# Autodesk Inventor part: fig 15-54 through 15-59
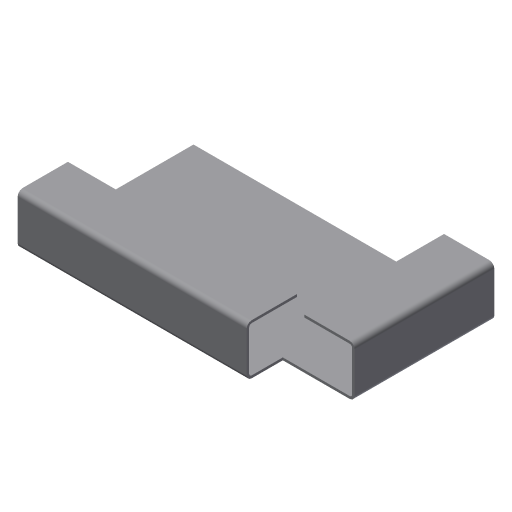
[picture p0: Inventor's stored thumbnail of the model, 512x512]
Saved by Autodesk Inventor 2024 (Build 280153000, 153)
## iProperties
Created: 2008-06
Part Number: fig 15-54 through 15-59
Material: Generic
Document SubType Name: Sheet Metal
Designer: CADCIM
Density: 1 g/cm^3
Sheet Metal Rule: Default_mm
Appearance: Default
Author: CADCIM
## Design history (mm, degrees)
node "Face1"
  sketch "Sketch1"
    geometry: L1 (-32.219, 35.011)-(27.554, 35.011); L2 (27.554, 35.011)-(27.554, 7.255); L3 (13.281, 0.063)-(-32.219, 0.063); L4 (-32.219, 0.063)-(-32.219, 35.011); L5 (13.281, 0.063)-(13.281, 7.255); L6 (13.281, 7.255)-(27.554, 7.255)
    constraints: 12 end point, 2 parallel, 2 perpendicular, 1 horizontal, 1 vertical
node "Flange5"
node "Flange6"
node "Flange7"
node "Flange8"
body "Solid1"
face "Plate1" dims "d90" = 0.5 (= Thickness)
sketch "Sketch6"
  geometry: L1 (0, 10)-(-45.501, 10); L2 (-45.501, 10)-(-45.501, 0); 1 other entity
  constraints: 4 end point, 4 other
face "Plate6" dims "d50" = 0.5 (= BendReliefWidth), "d51" = 0.25 (= BendReliefDepth), "d52" = 1 (= MinimumRemnant), "d53" = 0.5 (= BendRadius), "d54" = 10, "d55" = 90 deg, "d56" = 0.5 (= BendRadius), "d57" = 2 (= CornerReliefSize), "d58" = 0.5 (= GapSize), "d59" = 0.5 (= JacobiRadiusSize), "d90" = 0.5 (= Thickness), "SeamGap" = 0.01
bend "Bend5" dims "d50" = 0.5 (= BendReliefWidth), "d51" = 0.25 (= BendReliefDepth), "d52" = 1 (= MinimumRemnant), "d53" = 0.5 (= BendRadius), "d54" = 10, "d55" = 90 deg, "d56" = 0.5 (= BendRadius), "d90" = 0.5 (= Thickness), "SeamGap" = 0.01
feature "Corner5" dims "d54" = 10, "d55" = 90 deg, "d57" = 2 (= CornerReliefSize), "d58" = 0.5 (= GapSize), "d59" = 0.5 (= JacobiRadiusSize)
sketch "Sketch7"
  geometry: L1 (0, 10)-(-45.501, 10); L2 (-45.501, 10)-(-45.501, 0); 1 other entity
  constraints: 4 end point, 4 other
face "Plate7" dims "d60" = 0.5 (= BendReliefWidth), "d61" = 0.25 (= BendReliefDepth), "d62" = 1 (= MinimumRemnant), "d63" = 0.5 (= BendRadius), "d64" = 10, "d65" = 90 deg, "d66" = 0.5 (= BendRadius), "d67" = 2 (= CornerReliefSize), "d68" = 0.5 (= GapSize), "d69" = 0.5 (= JacobiRadiusSize), "d90" = 0.5 (= Thickness), "SeamGap" = 0.01
bend "Bend6" dims "d60" = 0.5 (= BendReliefWidth), "d61" = 0.25 (= BendReliefDepth), "d62" = 1 (= MinimumRemnant), "d63" = 0.5 (= BendRadius), "d64" = 10, "d65" = 90 deg, "d66" = 0.5 (= BendRadius), "d90" = 0.5 (= Thickness), "SeamGap" = 0.01
feature "Corner6" dims "d64" = 10, "d65" = 90 deg, "d67" = 2 (= CornerReliefSize), "d68" = 0.5 (= GapSize), "d69" = 0.5 (= JacobiRadiusSize)
sketch "Sketch8"
  geometry: L1 (0, 10)-(-27.756, 10); L2 (-27.756, 10)-(-27.756, 0); 1 other entity
  constraints: 4 end point, 4 other
face "Plate8" dims "d70" = 0.5 (= BendReliefWidth), "d71" = 0.25 (= BendReliefDepth), "d72" = 1 (= MinimumRemnant), "d73" = 0.5 (= BendRadius), "d74" = 10, "d75" = 90 deg, "d76" = 0.5 (= BendRadius), "d77" = 2 (= CornerReliefSize), "d78" = 0.5 (= GapSize), "d79" = 0.5 (= JacobiRadiusSize), "d90" = 0.5 (= Thickness), "SeamGap" = 0.01
bend "Bend7" dims "d70" = 0.5 (= BendReliefWidth), "d71" = 0.25 (= BendReliefDepth), "d72" = 1 (= MinimumRemnant), "d73" = 0.5 (= BendRadius), "d74" = 10, "d75" = 90 deg, "d76" = 0.5 (= BendRadius), "d90" = 0.5 (= Thickness), "SeamGap" = 0.01
feature "Corner7" dims "d74" = 10, "d75" = 90 deg, "d77" = 2 (= CornerReliefSize), "d78" = 0.5 (= GapSize), "d79" = 0.5 (= JacobiRadiusSize)
sketch "Sketch9"
  geometry: L1 (-10, 0)-(-10, -27.756); L2 (-10, -27.756)-(0, -27.756); 1 other entity
  constraints: 4 end point, 4 other
face "Plate9" dims "d80" = 0.5 (= BendReliefWidth), "d81" = 0.25 (= BendReliefDepth), "d82" = 1 (= MinimumRemnant), "d83" = 0.5 (= BendRadius), "d84" = 10, "d85" = 90 deg, "d86" = 0.5 (= BendRadius), "d87" = 2 (= CornerReliefSize), "d88" = 0.5 (= GapSize), "d89" = 0.5 (= JacobiRadiusSize), "d90" = 0.5 (= Thickness), "SeamGap" = 0.01
bend "Bend8" dims "d80" = 0.5 (= BendReliefWidth), "d81" = 0.25 (= BendReliefDepth), "d82" = 1 (= MinimumRemnant), "d83" = 0.5 (= BendRadius), "d84" = 10, "d85" = 90 deg, "d86" = 0.5 (= BendRadius), "d90" = 0.5 (= Thickness), "SeamGap" = 0.01
feature "Corner8" dims "d84" = 10, "d85" = 90 deg, "d87" = 2 (= CornerReliefSize), "d88" = 0.5 (= GapSize), "d89" = 0.5 (= JacobiRadiusSize)
other parameters: "Thickness" = 0.5, "BendRadius" = 0.5 (= Thickness), "BendReliefWidth" = 0.5 (= Thickness), "BendReliefDepth" = 0.25 (= 0.5 x Thickness), "CornerReliefSize" = 2 (= 4 x Thickness), "MinimumRemnant" = 1 (= 2 x Thickness), "TransitionRadius" = 0.5 (= BendRadius), "JacobiRadiusSize" = 0.5 (= BendRadius), "d0" = 0.5 (= BendRadius), "GapSize" = 0.5 (= Thickness)
